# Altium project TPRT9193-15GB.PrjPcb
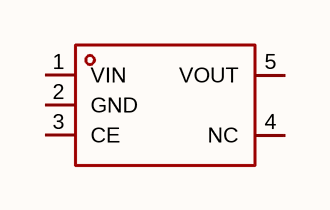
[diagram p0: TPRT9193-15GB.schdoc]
1 sheet, 1 parts. Net scope: global (net labels, ports and power ports of the same name join across sheets).

## Sheet TPRT9193-15GB.schdoc
size 127 x 101 mm

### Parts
U?  tprt9193-15gb  [SOT-23-5_L2.9-W1.6-P0.95-LS2.8-BR]  (value not drawn)

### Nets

Not connected (* = marked no-connect by the designer): U? 1(VIN) 2(GND) 3(CE) 4(NC) 5(VOUT)

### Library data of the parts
U? = tprt9193-15gb: 输出极性:正极;工作电压:6V;输出电压:1.5V;输出电流:300mA;电源纹波抑制比(PSRR):70dB@(1kHz);输出类型:固定;; Manufacturer: TECH PUBLIC(台舟); AddInBom: yes; ModelId: 7ba65df16e7b4570af156e925f9c37fe; ModelTransform: 114.173,114.173,0,90,0,0,0,0,0; Output Configuration: 正极; Voltage - Supply: 6V; Output Voltage: 1.5V; Output Current: 300mA; standby current: 70uA; Noise: 50uVrms; Output Type: 固定; Number of Outputs: 1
